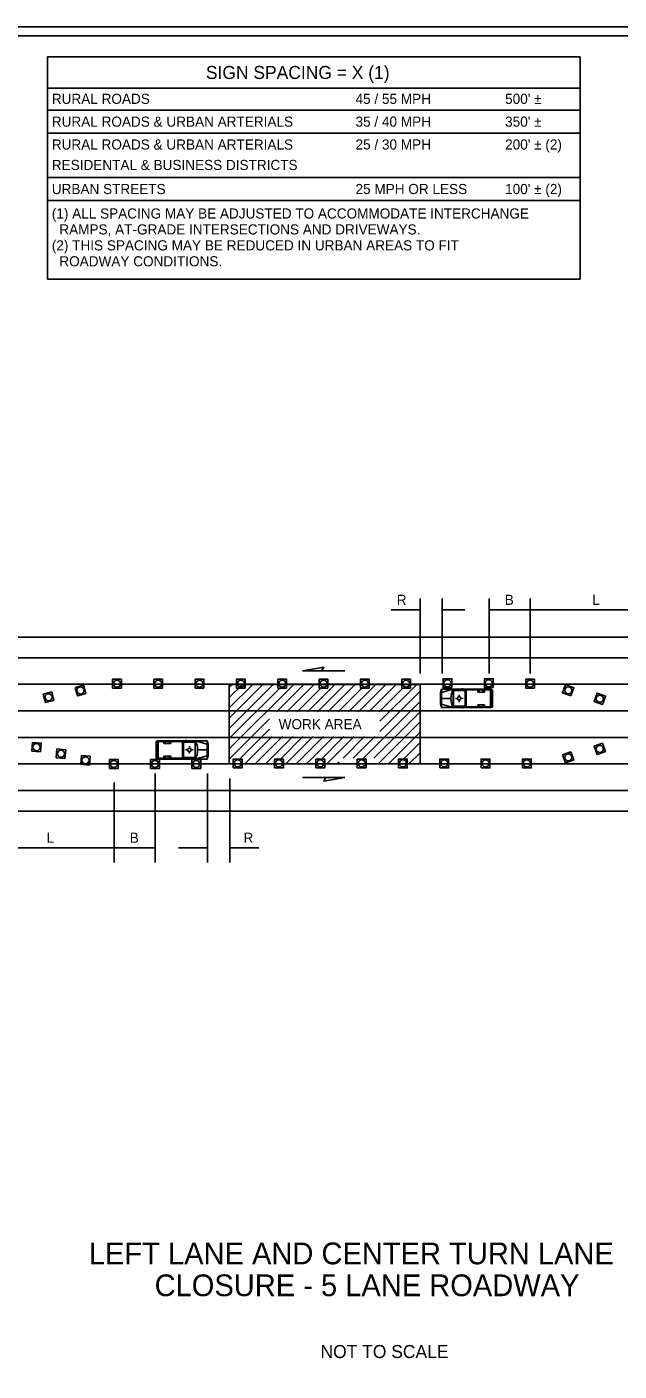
# Model space of a CAD drawing. Extents: x 99988 to 100172, y 99995 to 100047.
# Drawn here: x 100005.58 to 100009.66, y 100001.16 to 100010.44 of the extents above; entities that cross this region are included whole.
import ezdxf

# ---------------------------------------------------------------- set-up
doc = ezdxf.new("R2010")
doc.units = 0
for name, color, linetype in [('Default', 7, 'Continuous'), ('Level 15', 7, 'Continuous'), ('Level 20', 7, 'Continuous'), ('SH_DE_DetailBody1Text', 7, 'Continuous'), ('SH_DE_DetailHeading1Text', 7, 'Continuous'), ('SH_DE_DetailHeading3Text', 7, 'Continuous'), ('SH_GI_PlotLimits', 7, 'Continuous'), ('SH_GI_SheetBorder', 7, 'Continuous'), ('SH_GI_TrafficMvmntArrowRt1Lane', 7, 'Continuous'), ('SH_RS_ConstructionNoteFlag', 7, 'Continuous'), ('SH_TI_SignSpacing35to70Note', 7, 'Continuous'), ('TR_WZ_TrafficSafetyCone', 7, 'Continuous'), ('TR_WZ_TruckBuffer', 7, 'Continuous'), ('TR_WZ_WorkZoneDetails', 7, 'Continuous')]:
    doc.layers.add(name, color=color, linetype=linetype)

msp = doc.modelspace()

# ---------------------------------------------------------------- linework, layer by layer
at = {"layer": 'Default'}
msp.add_line((100013.6062, 100005.718), (100001.7239, 100005.7184), dxfattribs=at)
at = {"layer": 'Level 15'}
for p, q in [((100008.2901, 100006.4143), (100008.0901, 100006.4143)), ((100008.4429, 100006.4143), (100008.5981, 100006.4143)), ((100008.7672, 100006.4143), (100008.908, 100006.4143)), ((100009.0489, 100006.4143), (100008.908, 100006.4143)), ((100009.0489, 100006.4143), (100009.5067, 100006.4143)), ((100009.9645, 100006.4143), (100009.5067, 100006.4143)), ((100005.3052, 100004.7726), (100005.7422, 100004.7726)), ((100006.1792, 100004.7726), (100005.7422, 100004.7726)), ((100006.1792, 100004.7726), (100006.3203, 100004.7726)), ((100006.4614, 100004.7726), (100006.3203, 100004.7726)), ((100006.8237, 100004.7726), (100006.6237, 100004.7726)), ((100006.9765, 100004.7726), (100007.1765, 100004.7726))]:
    msp.add_line(p, q, dxfattribs=at)
at = {"layer": 'SH_GI_PlotLimits'}
msp.add_lwpolyline([(99999.3125, 99999.9375), (100015.8125, 99999.9375), (100015.8125, 100010.4375), (99999.3125, 100010.4375)], close=True, dxfattribs=at)
at = {"layer": 'SH_GI_SheetBorder'}
msp.add_line((100000, 100010.375), (100015.75, 100010.375), dxfattribs=at)
at = {"layer": 'SH_GI_TrafficMvmntArrowRt1Lane'}
for p, q in [((100007.6105, 100005.9935), (100007.7712, 100005.9935)), ((100007.6397, 100005.2591), (100007.4789, 100005.2591))]:
    msp.add_line(p, q, dxfattribs=at)
for points in [[(100007.4795, 100005.9935), (100007.6254, 100006.0193), (100007.6105, 100005.9935)], [(100007.7707, 100005.2591), (100007.6248, 100005.2334), (100007.6397, 100005.2591)]]:
    msp.add_lwpolyline(points, close=True, dxfattribs=at)
at = {"layer": 'SH_TI_SignSpacing35to70Note'}
for p, q in [((100005.7181, 100010.0156), (100009.3936, 100010.0156)), ((100005.7181, 100009.8624), (100009.3936, 100009.8624)), ((100005.7181, 100009.705), (100009.3936, 100009.705)), ((100005.7181, 100009.3975), (100009.3936, 100009.3975)), ((100005.7181, 100009.2401), (100009.3936, 100009.2401)), ((100005.7181, 100008.6965), (100009.3936, 100008.6965))]:
    msp.add_line(p, q, dxfattribs=at)
for points in [[(100005.7181, 100010.0156), (100005.7181, 100010.2301), (100009.3936, 100010.2301), (100009.3936, 100010.0156)], [(100005.7181, 100008.6965), (100005.7181, 100010.0156)], [(100009.3936, 100010.0253), (100009.3936, 100008.6965)]]:
    msp.add_lwpolyline(points, dxfattribs=at)
at = {"layer": 'TR_WZ_TrafficSafetyCone'}
for points in [[(100005.9094, 100005.8803), (100005.9251, 100005.8217), (100005.9838, 100005.8374), (100005.968, 100005.896)], [(100006.2288, 100005.8749), (100006.2288, 100005.9357), (100006.1681, 100005.9357), (100006.1681, 100005.8749)], [(100006.5138, 100005.8749), (100006.5138, 100005.9357), (100006.4531, 100005.9357), (100006.4531, 100005.8749)], [(100006.7988, 100005.8749), (100006.7988, 100005.9357), (100006.7381, 100005.9357), (100006.7381, 100005.8749)], [(100007.0838, 100005.8749), (100007.0838, 100005.9357), (100007.0231, 100005.9357), (100007.0231, 100005.8749)], [(100007.3692, 100005.8749), (100007.3692, 100005.9357), (100007.3085, 100005.9357), (100007.3085, 100005.8749)], [(100007.6542, 100005.8749), (100007.6542, 100005.9357), (100007.5935, 100005.9357), (100007.5935, 100005.8749)], [(100007.9392, 100005.8749), (100007.9392, 100005.9357), (100007.8785, 100005.9357), (100007.8785, 100005.8749)], [(100008.2242, 100005.8749), (100008.2242, 100005.9357), (100008.1635, 100005.9357), (100008.1635, 100005.8749)], [(100008.5092, 100005.8784), (100008.5092, 100005.9391), (100008.4485, 100005.9391), (100008.4485, 100005.8784)], [(100008.7942, 100005.8784), (100008.7942, 100005.9391), (100008.7335, 100005.9391), (100008.7335, 100005.8784)], [(100009.0792, 100005.8749), (100009.0792, 100005.9357), (100009.0185, 100005.9357), (100009.0185, 100005.8749)], [(100009.3306, 100005.821), (100009.3514, 100005.8781), (100009.2943, 100005.8989), (100009.2735, 100005.8418)], [(100005.6893, 100005.8335), (100005.705, 100005.7749), (100005.7637, 100005.7906), (100005.748, 100005.8493)], [(100009.5479, 100005.7628), (100009.5687, 100005.8198), (100009.5116, 100005.8406), (100009.4909, 100005.7835)], [(100005.6708, 100005.4348), (100005.6761, 100005.4953), (100005.6156, 100005.5006), (100005.6103, 100005.4401)], [(100005.8399, 100005.3895), (100005.8452, 100005.45), (100005.7847, 100005.4553), (100005.7794, 100005.3948)], [(100009.3306, 100005.4363), (100009.3514, 100005.3792), (100009.2943, 100005.3585), (100009.2735, 100005.4155)], [(100009.5479, 100005.4945), (100009.5687, 100005.4375), (100009.5116, 100005.4167), (100009.4909, 100005.4738)], [(100006.0089, 100005.3443), (100006.0142, 100005.4048), (100005.9537, 100005.41), (100005.9484, 100005.3495)], [(100006.146, 100005.3213), (100006.2068, 100005.3213), (100006.2068, 100005.382), (100006.146, 100005.382)], [(100006.431, 100005.3213), (100006.4918, 100005.3213), (100006.4918, 100005.382), (100006.431, 100005.382)], [(100006.716, 100005.3213), (100006.7768, 100005.3213), (100006.7768, 100005.382), (100006.716, 100005.382)], [(100007.001, 100005.3249), (100007.0618, 100005.3249), (100007.0618, 100005.3856), (100007.001, 100005.3856)], [(100007.286, 100005.3249), (100007.3468, 100005.3249), (100007.3468, 100005.3856), (100007.286, 100005.3856)], [(100007.571, 100005.3249), (100007.6318, 100005.3249), (100007.6318, 100005.3856), (100007.571, 100005.3856)], [(100007.856, 100005.3249), (100007.9168, 100005.3249), (100007.9168, 100005.3856), (100007.856, 100005.3856)], [(100008.141, 100005.3249), (100008.2018, 100005.3249), (100008.2018, 100005.3856), (100008.141, 100005.3856)], [(100008.426, 100005.3249), (100008.4868, 100005.3249), (100008.4868, 100005.3856), (100008.426, 100005.3856)], [(100008.711, 100005.3249), (100008.7718, 100005.3249), (100008.7718, 100005.3856), (100008.711, 100005.3856)], [(100008.996, 100005.3249), (100009.0568, 100005.3249), (100009.0568, 100005.3856), (100008.996, 100005.3856)]]:
    msp.add_lwpolyline(points, close=True, dxfattribs=at)
for centre in [(100005.9466, 100005.8588), (100006.1984, 100005.9053), (100006.4834, 100005.9053), (100006.7684, 100005.9053), (100007.0534, 100005.9053), (100007.3389, 100005.9053), (100007.6239, 100005.9053), (100007.9089, 100005.9053), (100008.1939, 100005.9053), (100008.4789, 100005.9087), (100008.7639, 100005.9087), (100009.0489, 100005.9053), (100009.3125, 100005.8599), (100005.7265, 100005.8121), (100009.5298, 100005.8017), (100005.6432, 100005.4677), (100005.8123, 100005.4224), (100009.3125, 100005.3974), (100009.5298, 100005.4556), (100005.9813, 100005.3771), (100006.1764, 100005.3516), (100006.4614, 100005.3516), (100006.7464, 100005.3516), (100007.0314, 100005.3552), (100007.3164, 100005.3552), (100007.6014, 100005.3552), (100007.8864, 100005.3552), (100008.1714, 100005.3552), (100008.4564, 100005.3552), (100008.7414, 100005.3552), (100009.0264, 100005.3552)]:
    msp.add_circle(centre, 0.0244, dxfattribs=at)
at = {"layer": 'TR_WZ_TruckBuffer'}
for p, q in [((100008.4377, 100005.8673), (100008.4297, 100005.8419)), ((100008.4297, 100005.7666), (100008.4297, 100005.8419)), ((100008.4377, 100005.7411), (100008.4377, 100005.8673)), ((100008.4377, 100005.8673), (100008.6006, 100005.8673)), ((100008.4377, 100005.8442), (100008.5192, 100005.8673)), ((100008.4377, 100005.8042), (100008.5032, 100005.8042)), ((100008.5192, 100005.7411), (100008.5192, 100005.8673)), ((100008.5206, 100005.7411), (100008.5206, 100005.8673)), ((100008.5292, 100005.8576), (100008.5206, 100005.8673)), ((100008.5206, 100005.8576), (100008.6006, 100005.8576)), ((100008.5337, 100005.8042), (100008.5446, 100005.8042)), ((100008.5597, 100005.7792), (100008.5598, 100005.7894)), ((100008.5604, 100005.8285), (100008.5601, 100005.819)), ((100008.5719, 100005.8045), (100008.5719, 100005.8045)), ((100008.5864, 100005.8047), (100008.5735, 100005.8045)), ((100008.5784, 100005.8691), (100008.5882, 100005.8691)), ((100008.6006, 100005.7411), (100008.6006, 100005.8673)), ((100008.7805, 100005.8673), (100008.603, 100005.8673)), ((100008.603, 100005.7411), (100008.603, 100005.8673)), ((100008.7754, 100005.8623), (100008.608, 100005.8623)), ((100008.608, 100005.7462), (100008.608, 100005.8623)), ((100008.688, 100005.8623), (100008.688, 100005.8478)), ((100008.7354, 100005.8478), (100008.688, 100005.8478)), ((100008.6966, 100005.8623), (100008.6966, 100005.8478)), ((100008.726, 100005.8623), (100008.726, 100005.8478)), ((100008.7354, 100005.8623), (100008.7354, 100005.8478)), ((100008.7754, 100005.7462), (100008.7754, 100005.8623)), ((100008.7805, 100005.7411), (100008.7805, 100005.8673)), ((100008.7849, 100005.8653), (100008.7811, 100005.8653)), ((100008.7811, 100005.7432), (100008.7811, 100005.8653)), ((100008.7888, 100005.8131), (100008.7811, 100005.8108)), ((100008.7888, 100005.7953), (100008.7811, 100005.7977)), ((100008.7867, 100005.8042), (100008.7831, 100005.8042)), ((100008.7849, 100005.8025), (100008.7849, 100005.806)), ((100008.7888, 100005.7471), (100008.7888, 100005.8614)), ((100008.4377, 100005.7411), (100008.4297, 100005.7666)), ((100008.4377, 100005.7642), (100008.5192, 100005.7411)), ((100008.4377, 100005.7411), (100008.6006, 100005.7411)), ((100008.5206, 100005.7411), (100008.531, 100005.7509)), ((100008.5206, 100005.7509), (100008.6006, 100005.7509)), ((100008.5784, 100005.7394), (100008.5882, 100005.7394)), ((100008.7805, 100005.7411), (100008.603, 100005.7411)), ((100008.7754, 100005.7462), (100008.608, 100005.7462)), ((100008.7354, 100005.7607), (100008.688, 100005.7607)), ((100008.688, 100005.7462), (100008.688, 100005.7607)), ((100008.6966, 100005.7462), (100008.6966, 100005.7607)), ((100008.726, 100005.7462), (100008.726, 100005.7607)), ((100008.7354, 100005.7462), (100008.7354, 100005.7607)), ((100008.7849, 100005.7432), (100008.7811, 100005.7432)), ((100006.4694, 100005.5058), (100006.4694, 100005.3914)), ((100006.4732, 100005.5097), (100006.4771, 100005.5097)), ((100006.4771, 100005.5097), (100006.4771, 100005.3876)), ((100006.4777, 100005.5117), (100006.6551, 100005.5117)), ((100006.4777, 100005.5117), (100006.4777, 100005.3855)), ((100006.4827, 100005.5067), (100006.4827, 100005.3906)), ((100006.4827, 100005.5067), (100006.6501, 100005.5067)), ((100006.5227, 100005.5067), (100006.5227, 100005.4922)), ((100006.5322, 100005.5067), (100006.5322, 100005.4922)), ((100006.5615, 100005.5067), (100006.5615, 100005.4922)), ((100006.5701, 100005.5067), (100006.5701, 100005.4922)), ((100006.6501, 100005.5067), (100006.6501, 100005.3906)), ((100006.6551, 100005.5117), (100006.6551, 100005.3855)), ((100006.6575, 100005.5117), (100006.6575, 100005.3855)), ((100006.8204, 100005.5117), (100006.6575, 100005.5117)), ((100006.6797, 100005.5135), (100006.6699, 100005.5135)), ((100006.7375, 100005.5117), (100006.7271, 100005.502)), ((100006.7375, 100005.5117), (100006.7375, 100005.3855)), ((100006.739, 100005.5117), (100006.739, 100005.3855)), ((100006.8204, 100005.4886), (100006.739, 100005.5117)), ((100006.8204, 100005.5117), (100006.8204, 100005.3855)), ((100006.8204, 100005.5117), (100006.8284, 100005.4863)), ((100006.4694, 100005.4575), (100006.4771, 100005.4551)), ((100006.4694, 100005.4397), (100006.4771, 100005.4421)), ((100006.4714, 100005.4486), (100006.475, 100005.4486)), ((100006.4732, 100005.4504), (100006.4732, 100005.4469)), ((100006.5227, 100005.4922), (100006.5701, 100005.4922)), ((100006.7375, 100005.502), (100006.6575, 100005.502)), ((100006.6718, 100005.4481), (100006.6846, 100005.4484)), ((100006.6862, 100005.4484), (100006.6862, 100005.4484)), ((100006.6978, 100005.4244), (100006.698, 100005.4338)), ((100006.6984, 100005.4736), (100006.6984, 100005.4634)), ((100006.7244, 100005.4487), (100006.7135, 100005.4487)), ((100006.8204, 100005.4486), (100006.7549, 100005.4486)), ((100006.8204, 100005.3855), (100006.8284, 100005.411)), ((100006.8284, 100005.4863), (100006.8284, 100005.411)), ((100006.4732, 100005.3876), (100006.4771, 100005.3876)), ((100006.4777, 100005.3855), (100006.6551, 100005.3855)), ((100006.4827, 100005.3906), (100006.6501, 100005.3906)), ((100006.5227, 100005.3906), (100006.5227, 100005.4051)), ((100006.5227, 100005.4051), (100006.5701, 100005.4051)), ((100006.5322, 100005.3906), (100006.5322, 100005.4051)), ((100006.5615, 100005.3906), (100006.5615, 100005.4051)), ((100006.5701, 100005.3906), (100006.5701, 100005.4051)), ((100006.7375, 100005.3953), (100006.6575, 100005.3953)), ((100006.8204, 100005.3855), (100006.6575, 100005.3855)), ((100006.6797, 100005.3837), (100006.6699, 100005.3837)), ((100006.7289, 100005.3953), (100006.7375, 100005.3855)), ((100006.8204, 100005.4086), (100006.739, 100005.3855))]:
    msp.add_line(p, q, dxfattribs=at)
for centre, radius in [((100008.5598, 100005.8042), 0.0122), ((100008.7849, 100005.8042), 0.00178), ((100006.4732, 100005.4486), 0.00178), ((100006.6984, 100005.4486), 0.0122)]:
    msp.add_circle(centre, radius, dxfattribs=at)
for centre, radius, start, end in [((100008.6356, 100005.8042), 0.1324, 151.55054, 208.46005), ((100008.7849, 100005.8614), 0.00385, 0, 90), ((100008.7849, 100005.7471), 0.00385, 270, 359.99999), ((100006.4732, 100005.5058), 0.00385, 90, 179.99999), ((100006.6225, 100005.4486), 0.1324, 331.55054, 28.46005), ((100006.4732, 100005.3914), 0.00385, 180, 270)]:
    msp.add_arc(centre, radius, start, end, dxfattribs=at)
at = {"layer": 'TR_WZ_WorkZoneDetails'}
for p, q in [((100008.2901, 100006.4943), (100008.2901, 100005.9751)), ((100008.4429, 100006.4943), (100008.4429, 100005.9751)), ((100008.7672, 100005.9751), (100008.7672, 100006.4943)), ((100009.0489, 100005.9751), (100009.0489, 100006.4943)), ((100001.7239, 100006.2268), (100012.9775, 100006.2268)), ((100001.7239, 100006.0851), (100013.6062, 100006.0851)), ((100001.7239, 100005.9017), (100013.6059, 100005.9017)), ((100006.9733, 100005.8804), (100006.9936, 100005.9007)), ((100006.9733, 100005.8097), (100007.0643, 100005.9007)), ((100006.9733, 100005.7389), (100007.135, 100005.9007)), ((100006.9733, 100005.6682), (100007.2057, 100005.9007)), ((100006.9733, 100005.5975), (100007.2764, 100005.9007)), ((100006.9733, 100005.4561), (100007.4179, 100005.9007)), ((100006.9733, 100005.5268), (100007.3268, 100005.8803)), ((100007.3002, 100005.7123), (100007.4886, 100005.9007)), ((100007.3709, 100005.7123), (100007.5593, 100005.9007)), ((100007.4416, 100005.7123), (100007.6096, 100005.8803)), ((100007.5123, 100005.7123), (100007.7007, 100005.9007)), ((100007.583, 100005.7123), (100007.7714, 100005.9007)), ((100007.6537, 100005.7123), (100007.8421, 100005.9007)), ((100007.7244, 100005.7123), (100007.8925, 100005.8803)), ((100007.7952, 100005.7123), (100007.9835, 100005.9007)), ((100007.8659, 100005.7123), (100008.0542, 100005.9007)), ((100007.9366, 100005.7123), (100008.125, 100005.9007)), ((100008.0073, 100005.7123), (100008.1753, 100005.8803)), ((100008.0123, 100005.6466), (100008.2664, 100005.9007)), ((100007.8995, 100005.3924), (100008.2901, 100005.783)), ((100008.0123, 100005.5759), (100008.2901, 100005.8537)), ((100007.9699, 100005.392), (100008.2901, 100005.7122)), ((100006.9733, 100005.3854), (100007.2511, 100005.6632)), ((100008.0004, 100005.3519), (100008.2901, 100005.6415)), ((100001.7239, 100005.535), (100013.6062, 100005.535)), ((100007.0388, 100005.3802), (100007.2511, 100005.5925)), ((100007.0812, 100005.3519), (100007.2696, 100005.5402)), ((100007.1519, 100005.3519), (100007.3403, 100005.5402)), ((100007.2226, 100005.3519), (100007.411, 100005.5402)), ((100007.3217, 100005.3802), (100007.4817, 100005.5402)), ((100007.364, 100005.3519), (100007.5524, 100005.5402)), ((100007.4347, 100005.3519), (100007.6231, 100005.5402)), ((100007.5054, 100005.3519), (100007.6938, 100005.5402)), ((100007.6045, 100005.3802), (100007.7645, 100005.5402)), ((100007.6469, 100005.3519), (100007.8352, 100005.5402)), ((100007.7581, 100005.3924), (100007.906, 100005.5402)), ((100007.8288, 100005.3924), (100007.9767, 100005.5402)), ((100008.0711, 100005.3519), (100008.2901, 100005.5708)), ((100008.1702, 100005.3802), (100008.2901, 100005.5001)), ((100008.2126, 100005.3519), (100008.2901, 100005.4294)), ((100001.7239, 100005.3517), (100013.6062, 100005.3517)), ((100007.5762, 100005.3519), (100007.5764, 100005.3521)), ((100007.7176, 100005.3519), (100007.7308, 100005.3651)), ((100008.1418, 100005.3519), (100008.1464, 100005.3564)), ((100008.2833, 100005.3519), (100008.2901, 100005.3587)), ((100006.4614, 100005.2855), (100006.4614, 100004.6726)), ((100006.8237, 100005.2855), (100006.8237, 100004.6726)), ((100006.9765, 100005.2519), (100006.9765, 100004.6726)), ((100001.7276, 100005.1683), (100013.5994, 100005.1683)), ((100006.1792, 100005.2249), (100006.1792, 100004.6726)), ((100002.4167, 100005.0266), (100013.6016, 100005.0266))]:
    msp.add_line(p, q, dxfattribs=at)
msp.add_lwpolyline([(100006.9733, 100005.3519), (100008.2901, 100005.3519), (100008.2901, 100005.9007), (100006.9733, 100005.9007)], close=True, dxfattribs=at)

# ---------------------------------------------------------------- texts
at = {"layer": 'Level 20'}
for s, p in [('B', (100008.8743, 100006.4493)), ('L', (100009.4776, 100006.4493))]:
    msp.add_text(s, height=0.07, rotation=360, dxfattribs=at).set_placement(p)
for s, p in [('L', (100005.7131, 100004.8076)), ('B', (100006.2866, 100004.8076))]:
    msp.add_text(s, height=0.07, dxfattribs=at).set_placement(p)
at = {"layer": 'SH_DE_DetailBody1Text'}
msp.add_text('WORK AREA', height=0.07, dxfattribs=at).set_placement((100007.3142, 100005.5913))
at = {"layer": 'SH_DE_DetailHeading1Text'}
for s, p in [('LEFT LANE AND CENTER TURN LANE ', (100006.0044, 100001.8994)), ('CLOSURE - 5 LANE ROADWAY', (100006.4582, 100001.6794))]:
    msp.add_text(s, height=0.15, dxfattribs=at).set_placement(p)
at = {"layer": 'SH_DE_DetailHeading3Text'}
msp.add_text('NOT TO SCALE', height=0.09, dxfattribs=at).set_placement((100007.603, 100001.2525))
at = {"layer": 'SH_RS_ConstructionNoteFlag'}
for p in [(100008.1289, 100006.4493), (100007.0715, 100004.8076)]:
    msp.add_text('R', height=0.07, dxfattribs=at).set_placement(p)
at = {"layer": 'SH_TI_SignSpacing35to70Note'}
for s, height, p in [('SIGN SPACING = X (1)', 0.09, (100006.8122, 100010.0779)), ('RURAL ROADS', 0.07, (100005.749, 100009.9061)), ('45 / 55 MPH', 0.07, (100007.8446, 100009.9061)), ("500' ±", 0.07, (100008.8766, 100009.9061)), ('RURAL ROADS & URBAN ARTERIALS', 0.07, (100005.749, 100009.7487)), ('35 / 40 MPH', 0.07, (100007.8446, 100009.7487)), ("350' ± ", 0.07, (100008.8766, 100009.7487)), ('RURAL ROADS & URBAN ARTERIALS', 0.07, (100005.749, 100009.5909)), ('25 / 30 MPH', 0.07, (100007.8446, 100009.5912)), ("200' ± (2)", 0.07, (100008.8766, 100009.5912)), ('RESIDENTAL & BUSINESS DISTRICTS', 0.07, (100005.749, 100009.4498)), ('URBAN STREETS', 0.07, (100005.749, 100009.2838)), ('25 MPH OR LESS', 0.07, (100007.8446, 100009.2838)), ("100' ± (2) ", 0.07, (100008.8766, 100009.2838)), ('(1) ALL SPACING MAY BE ADJUSTED TO ACCOMMODATE INTERCHANGE ', 0.07, (100005.749, 100009.1151)), ('  RAMPS, AT-GRADE INTERSECTIONS AND DRIVEWAYS.', 0.07, (100005.749, 100009.0051)), ('(2) THIS SPACING MAY BE REDUCED IN URBAN AREAS TO FIT  ', 0.07, (100005.749, 100008.8951)), ('  ROADWAY CONDITIONS.', 0.07, (100005.749, 100008.7851))]:
    msp.add_text(s, height=height, dxfattribs=at).set_placement(p)

doc.saveas('drawing.dxf')
